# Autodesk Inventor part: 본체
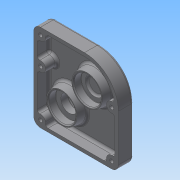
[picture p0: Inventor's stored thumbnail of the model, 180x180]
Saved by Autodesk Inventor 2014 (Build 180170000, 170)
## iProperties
Created: 2015-11
Part Number: 본체
Material: 일반
Document SubType Name: Modeling
Designer: net
Density: 1 g/cm^3
Appearance: 기본값
Author: net
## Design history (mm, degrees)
sketch "스케치1"
  geometry: L1 (-50, 51.5)-(-50, -51.5); L2 (-50, -51.5)-(50, -51.5); L3 (50, -51.5)-(50, 11.5); L4 (-50, 51.5)-(10, 51.5); A1 r 40 centre (10, 11.5) between (50, 11.5) and (10, 51.5); 3 further points
  constraints: 8 end point, 2 midpoint, 2 perpendicular, 2 point on circle, 1 centre point, 1 horizontal alignment, 1 parallel, 1 tangent, 1 vertical, 1 vertical alignment
  dimensions: "d0" = 103 distance between parallel lines of L2 L4; "d1" = 100 distance of L1.end L2.end; "d2" = 40 radius of A1; "d3" = 63.00001 distance from line of L2 A1.centre
extrude "돌출1" new body sketch "스케치1" stored distance "d4" = 18; taper "d5" = 0 deg
fillet "모깎기1" dims "d6" = 8
sketch "스케치2"
  geometry: L1 (50, -43.5)-(50, 11.5) reference; L2 (10, 51.5)-(-42, 51.5) reference; L3 (-50, 43.5)-(-50, -43.5) reference; L4 (-42, -51.5)-(42, -51.5) reference; L5 (46, 7.028)-(46, -39.028); L6 (37.528, -47.5)-(-37.528, -47.5); L7 (-46, -39.028)-(-46, 7.028); L8 (-46, 15.972)-(-46, 39.028); L9 (10, 47.5)-(-37.528, 47.5); A1 r 8 centre (42, -43.5) between (42, -51.5) and (50, -43.5) reference; A2 r 40 centre (10, 11.5) between (50, 11.5) and (10, 51.5) reference; A3 r 8 centre (-42, 43.5) between (-42, 51.5) and (-50, 43.5) reference; A4 r 8 centre (-42, -43.5) between (-50, -43.5) and (-42, -51.5) reference; A5 r 6 centre (-42, 43.5) between (-46, 39.028) and (-37.528, 47.5); A6 r 6 centre (-42, -43.5) between (-37.528, -47.5) and (-46, -39.028); A7 r 6 centre (42, -43.5) between (46, -39.028) and (37.528, -47.5); A8 r 6 centre (42, 11.5) between (45.688, 16.233) and (46, 7.028); A9 r 6 centre (-42, 11.5) between (-46, 7.028) and (-46, 15.972); A10 r 36 centre (10, 11.5) between (45.688, 16.233) and (10, 47.5); 1 further point
  constraints: 12 point on circle, 10 end point, 6 centre point, 4 equal radius, 3 coincident, 2 vertical alignment, 1 perpendicular
  dimensions: "d8" = 6 radius of A5; "d9" = 32 vertical distance of A8.centre A3.centre; "d10" = 63 distance from line of L4 A9.centre; "d12" = 36 radius of A10; "d13" = 4 distance between parallel lines of L2 L9; "d14" = 4 distance between parallel lines of L8 L3; "d15" = 4 distance between parallel lines of L7 L3; "d16" = 4 distance between parallel lines of L4 L6; "d17" = 4 distance between parallel lines of L5 L1
extrude "돌출2" cut sketch "스케치2" distance "d18" = 14; taper "d19" = 0 deg
sketch "스케치4"
  geometry: C1 r 20 at (10, 11.5); A1 r 36 centre (10, 11.5) between (45.688, 16.233) and (10, 47.5) reference; 1 further point
  constraints: 1 centre point, 1 coincident
  dimensions: "d23" = 40 diameter of C1
extrude "돌출3" join sketch "스케치4" distance "d24" = 11; taper "d25" = -10 deg
sketch "스케치5"
  geometry: C1 r 18.06 at (0, 0) reference; C2 r 16 at (0, 0); C3 r 11 at (0, 0); 1 further point
  constraints: 2 centre point, 2 coincident
  dimensions: "d27" = 32 diameter of C2; "d28" = 22 diameter of C3
extrude "돌출4" cut sketch "스케치5" distance "d29" = 9; taper "d30" = 0 deg
extrude "돌출5" cut sketch "스케치5" distance "d31" = 11; taper "d32" = 0 deg
sketch "스케치6"
  geometry: L1 (-50, 43.5)-(-50, -43.5) reference; L2 (-42, -51.5)-(42, -51.5) reference; C1 r 20 at (-20, -21.5); 1 further point
  constraints: 1 centre point
  dimensions: "d33" = 30 distance from line of L1 C1.centre; "d34" = 30 distance from line of L2 C1.centre; "d35" = 40 diameter of C1
extrude "돌출6" join sketch "스케치6" distance "d36" = 11; taper "d37" = -10 deg
sketch "스케치7"
  geometry: C1 r 18.06 at (0, 0) reference; C2 r 16 at (0, 0); 1 further point
  constraints: 1 centre point, 1 coincident
  dimensions: "d38" = 32 diameter of C2
extrude "돌출7" cut sketch "스케치7" distance "d39" = 9; taper "d40" = 0 deg
sketch "스케치8"
  geometry: C1 r 20 at (20, -21.5) reference; C2 r 25 at (20, -21.5); 1 further point
  constraints: 1 centre point, 1 coincident
  dimensions: "d41" = 50 diameter of C2
extrude "돌출8" join sketch "스케치8" distance "d42" = 15; taper "d43" = -10 deg
sketch "스케치9"
  geometry: C1 r 22.355 at (0, 0) reference; C2 r 14 at (0, 0); C3 r 12 at (0, 0); C4 r 12 at (0, 0); C5 r 10 at (0, 0); 1 further point
  constraints: 4 centre point, 4 coincident, 1 concentric
  dimensions: "d44" = 28 diameter of C2; "d45" = 24 diameter of C3; "d46" = 20 diameter of C5
extrude "돌출9" cut sketch "스케치9" distance "d47" = 11; taper "d48" = 0 deg
extrude "돌출10" cut sketch "스케치9" distance "d49" = 13; taper "d50" = 0 deg
extrude "돌출11" cut sketch "스케치9" stored distance "d51" = 13; taper "d52" = 0 deg
sketch "스케치10" dims "d53" = 36
  geometry: L1 (0, 0)-(0, 18); C1 r 22.355 at (0, 0) reference; 2 further points
  constraints: 2 coincident, 2 end point, 1 vertical, 1 vertical alignment, 2 other
hole "구멍1" sketch "스케치10" at (0, 18) diameter "d54" = 2.459; stored, may be unused: countersink angle "d58" = 90 deg, drill point angle "d60" = 118 deg; dims "d55" = 8, "d56" = 4, "d57" = 2, "d59" = 10
sketch "스케치13"
  geometry: L1 (37.528, 47.5)-(-10, 47.5) reference; L2 (-46, 7.028)-(-46, -39.028) reference; L3 (-37.528, -47.5)-(37.528, -47.5) reference; L4 (46, -39.028)-(46, 7.028) reference; L5 (46, 15.972)-(46, 39.028) reference; L6 (-50, -43.5)-(-50, 11.5) reference; L7 (-10, 51.5)-(42, 51.5) reference; L8 (50, 43.5)-(50, -43.5) reference; L9 (42, -51.5)-(-42, -51.5) reference; A1 r 36 centre (-10, 11.5) between (-10, 47.5) and (-45.688, 16.233) reference; A2 r 6 centre (-42, 11.5) between (-46, 7.028) and (-45.688, 16.233) reference; A3 r 6 centre (-42, -43.5) between (-37.528, -47.5) and (-46, -39.028) reference; A4 r 6 centre (42, -43.5) between (46, -39.028) and (37.528, -47.5) reference; A5 r 6 centre (42, 11.5) between (46, 15.972) and (46, 7.028) reference; A6 r 6 centre (42, 43.5) between (37.528, 47.5) and (46, 39.028) reference; A7 r 8 centre (-42, -43.5) between (-50, -43.5) and (-42, -51.5) reference; A8 r 40 centre (-10, 11.5) between (-10, 51.5) and (-50, 11.5) reference; A9 r 8 centre (42, 43.5) between (50, 43.5) and (42, 51.5) reference; A10 r 8 centre (42, -43.5) between (42, -51.5) and (50, -43.5) reference; 6 further points
  constraints: 5 coincident
hole "구멍3" sketch "스케치13" at (-42, 11.5), (-42, -43.5), (42, -43.5), (42, 11.5), (42, 43.5) diameter "d86" = 4.5; stored, may be unused: countersink angle "d90" = 90 deg, drill point angle "d92" = 118 deg; dims "d87" = 6, "d88" = 8, "d89" = 4.4, "d91" = 8
sketch "스케치12"
  geometry: L1 (50, -43.5)-(50, 43.5) reference; L2 (42, 51.5)-(-10, 51.5) reference; 2 further points
  constraints: 1 other
  dimensions: "d71" = 40 distance from line of L1 point (10, 31.5); "d72" = 20 distance from line of L2 point (10, 31.5)
feature "엠보싱1" sketch "스케치12" dims "d0" = 103, "d1" = 100, "d2" = 40, "d3" = 63.00001, "d73" = 0.5, "d74" = 0
fillet "모깎기2" dims "d75" = 3
fillet "모깎기3" dims "d76" = 3
fillet "모깎기4" dims "d77" = 0.3
fillet "모깎기5" dims "d78" = 0.3
fillet "모깎기6" dims "d79" = 3
chamfer "모따기1" distance "d80" = 1; stored, may be unused: second distance "d81" = 2, angle "d82" = 45 deg
fillet "모깎기7" dims "d83" = 3
fillet "모깎기8" dims "d84" = 3
fillet "모깎기9" dims "d85" = 3
node "솔리드1"
pattern_circular "원형 패턴1" dims angle "d62" = 360 deg
node "투영된 루프1"
